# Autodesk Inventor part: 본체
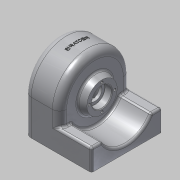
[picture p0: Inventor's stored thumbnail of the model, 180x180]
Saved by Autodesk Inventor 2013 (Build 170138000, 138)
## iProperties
Created: 2015-02
Part Number: 본체
Material: 알루미늄 6061
Document SubType Name: Modeling
Designer: Administrator
Density: 1 g/cm^3
Author: Administrator
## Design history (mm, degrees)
sketch "스케치1"
  geometry: L1 (-34.5, 0)-(34.5, 0); L2 (-34.5, 14)-(-34.5, 21.36); L3 (-34.5, 21.36)-(-24.5, 25); L4 (-24.5, 25)-(-24.5, 50); L5 (-24.5, 50)-(25.5, 50); L6 (25.5, 50)-(25.5, 20); L7 (25.5, 20)-(34.5, 20); L8 (34.5, 20)-(34.5, 0); L9 (34.5, 0)-(31.5, 0); L10 (31.5, 0)-(31.5, 10); L11 (31.5, 10)-(29.5, 10); L12 (29.5, 10)-(29.5, 14); L13 (29.5, 14)-(21.5, 14); L14 (21.5, 14)-(21.5, 46); L15 (21.5, 46)-(-20.5, 46); L16 (-20.5, 46)-(-20.5, 10); L17 (-20.5, 10)-(-24.5, 10); L18 (-24.5, 10)-(-24.5, 14); L19 (-24.5, 14)-(-34.5, 14); 3 further points
  constraints: 38 end point, 9 parallel, 4 perpendicular, 2 coincident, 2 horizontal, 2 midpoint, 1 collinear, 1 point on line, 1 vertical, 1 vertical alignment
  dimensions: "d0" = 69 distance of L1.start L1.end; "d1" = 20 diameter of L17 L1; "d2" = 28 diameter of L19 L1; "d3" = 50 diameter of L3.end L1; "d4" = 100 diameter of L5 L1; "d5" = 10 distance between parallel lines of L2 L4; "d6" = 50 distance of L4.end L5.end; "d7" = 40 diameter of L7 L1; "d8" = 20 diameter of L11 L1; "d9" = 28 diameter of L13 L1; "d10" = 2 distance between parallel lines of L10 L12; "d11" = 8 distance of L12.end L13.end; "d12" = 42 distance of L14.end L15.end; "d13" = 10 distance of L18.end L2.start; "d14" = 4 distance of L16.end L17.end; "d15" = 92 diameter of L15 L1; "d16" = 110 deg angle of L3 L4
revolve "회전1" sketch "스케치1" stored, may be unused: angle "d17" = 90 deg
sketch "스케치3"
  geometry: L1 (0, 50)-(50, 50); L2 (50, 50)-(50, -50); L3 (50, -50)-(0, -50); A1 r 50 centre (0, 0) between (0, 50) and (0, -50) reference
  constraints: 6 end point, 2 point on circle, 2 tangent, 1 horizontal, 1 perpendicular
  dimensions: "d18" = 50 distance of L1.start L1.end; "d19" = 100 distance of L1.end L2.end
extrude "돌출1" join sketch "스케치3" distance "d20" = 50; taper "d21" = 0 deg
sketch "스케치4"
  geometry: L1 (0, 100)-(50, 100) reference; L2 (0, 0)-(0, 100) reference; L3 (4, 96)-(46, 96); L4 (46, 96)-(46, 4); L5 (46, 4)-(4, 4); L6 (4, 4)-(4, 96); 1 further point
  constraints: 8 end point, 2 parallel, 1 horizontal, 1 perpendicular
  dimensions: "d22" = 42 distance of L4.end L5.end; "d23" = 92 distance of L3.end L4.end; "d24" = 4 distance between parallel lines of L2 L6; "d25" = 4 distance between parallel lines of L1 L3
extrude "돌출2" cut sketch "스케치4" distance "d26" = 50; taper "d27" = 0 deg
sketch "스케치5"
  geometry: L1 (-50, 0)-(0, 0) reference; L2 (0, 0)-(0, 100) reference; L3 (0, 100)-(-50, 100) reference; L4 (-30, 84.641)-(-30, 100); L5 (-30, 15.359)-(-30, 0); C1 r 25 at (-50, 50) reference; A1 r 40 centre (-50, 50) between (-30, 15.359) and (-30, 84.641)
  constraints: 4 end point, 2 perpendicular, 2 point on circle, 2 point on line, 1 centre point, 1 coincident, 1 collinear
  dimensions: "d28" = 80 diameter of A1; "d29" = 30 distance between parallel lines of L2 L4
extrude "돌출3" join sketch "스케치5" distance "d30" = 45; taper "d31" = 0 deg
node "작업 평면1"
sketch "스케치6"
  geometry: L1 (-25, 50)-(-25, -50) reference; 2 further points
  constraints: 1 horizontal alignment, 1 other
  dimensions: "d32" = 25 distance from line of L1 point (0, 0)
feature "엠보싱1" sketch "스케치6" dims "d33" = 0.5, "d34" = 0
fillet "모깎기1" dims "d35" = 10
fillet "모깎기2" dims "d36" = 6
fillet "모깎기3" dims "d37" = 0.3
chamfer "모따기1" distance "d38" = 1; stored, may be unused: second distance "d39" = 2, angle "d40" = 45 deg
fillet "모깎기4" dims "d41" = 3
fillet "모깎기5" dims "d42" = 3
fillet "모깎기6" dims "d43" = 3
sketch "스케치7" dims "d44" = 36
  geometry: C1 r 15 at (0, 0) reference; 5 further points
  constraints: 2 vertical alignment, 1 coincident, 7 other
  dimensions: "d47" = 360 deg dimension on point (0, 0) point (0, 18) (derived)
hole "구멍1" sketch "스케치7" at (0, 18), (-18, 0), (0, -18), (18, 0) diameter "d49" = 3.459; stored, may be unused: countersink angle "d53" = 90 deg, drill point angle "d55" = 118 deg; dims "d50" = 6, "d51" = 4, "d52" = 2, "d54" = 9
sketch "스케치8"
  geometry: L1 (-95, -7)-(-95, 87) reference; L2 (-86, 81.75)-(-53, 81.75); L3 (-53, 81.75)-(-53, -1.75); L4 (-53, -1.75)-(-86, -1.75); L5 (-86, -1.75)-(-86, 81.75); 7 further points
  constraints: 8 end point, 4 coincident, 2 midpoint, 2 parallel, 1 horizontal, 1 horizontal alignment, 1 perpendicular
  dimensions: "d56" = 33 distance of L3.end L4.end; "d57" = 83.5 distance of L2.end L3.end; "d58" = 9 distance between parallel lines of L1 L5
hole "구멍2" sketch "스케치8" at (-86, 81.75), (-53, 81.75), (-53, -1.75), (-86, -1.75) diameter "d59" = 5.134; stored, may be unused: countersink angle "d63" = 90 deg, drill point angle "d65" = 118 deg; dims "d60" = 10, "d61" = 4, "d62" = 2, "d64" = 13
node "솔리드1"
